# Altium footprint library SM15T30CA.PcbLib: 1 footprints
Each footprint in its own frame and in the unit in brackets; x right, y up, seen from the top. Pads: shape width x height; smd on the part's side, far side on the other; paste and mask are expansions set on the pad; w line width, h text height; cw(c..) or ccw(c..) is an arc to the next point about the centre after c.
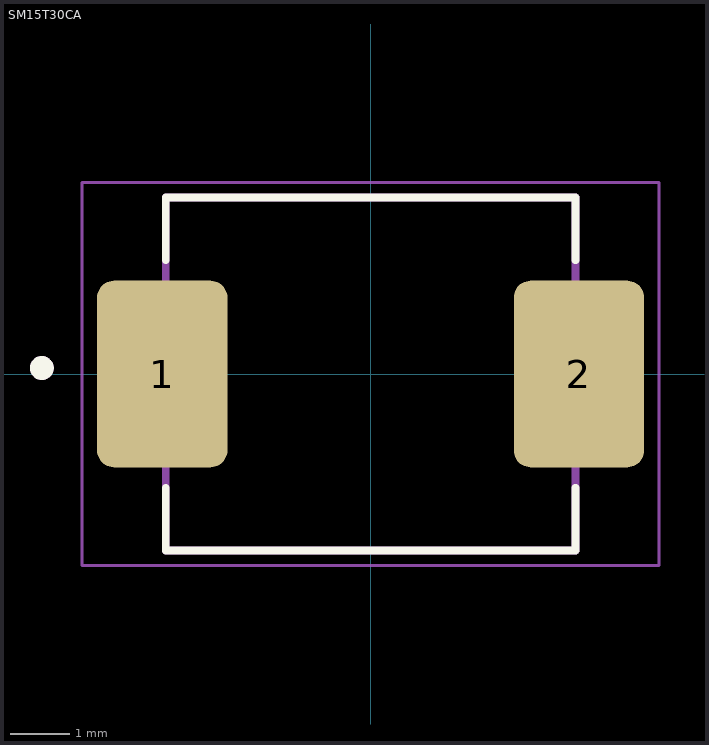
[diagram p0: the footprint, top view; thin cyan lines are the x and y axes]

## SM15T30CA [mm]
pads (2):
  rrect25% 2.18x3.12 smd: 1(-3.485,0) 2(3.485,0)
Top Overlay:
  circle w0.2: c-5.5,0.1 r0.1
  lines w0.127: -3.427,-1.9 -3.427,-2.953 3.427,-2.953 3.427,-1.9 ; -3.427,1.9 -3.427,2.953 3.427,2.953 3.427,1.9
Mechanical 13:
  circle w0.2: c-5.5,0.1 r0.1
  lines w0.127: -3.427,-2.953 3.427,-2.953 3.427,2.953 -3.427,2.953 -3.427,-2.953
Mechanical 15:
  lines w0.05: -4.825,-3.203 4.825,-3.203 4.825,3.203 -4.825,3.203 -4.825,-3.203
3D body "SM15T30CA.STEP": height 2.6, standoff -0.01, extent -3.937,-2.985 4.001,2.921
